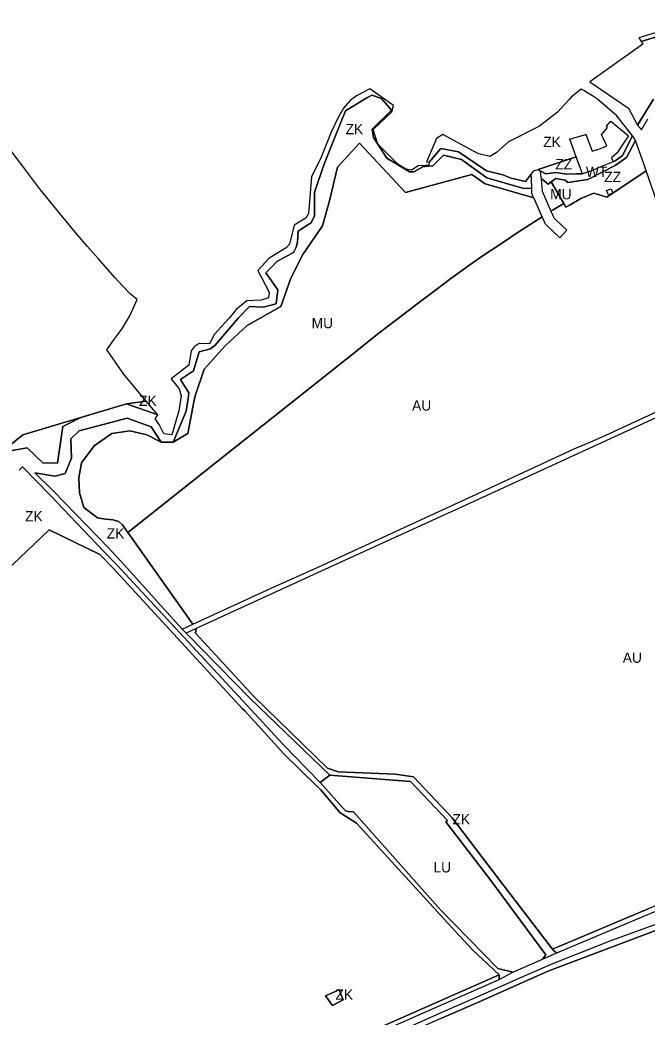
# Model space of a CAD drawing. Extents: x -522079 to -518833, y -1142398 to -1139961.
# Drawn here: x -521599 to -520990, y -1141061 to -1140093 of the extents above; entities that cross this region are included whole.
import ezdxf

# ---------------------------------------------------------------- set-up
doc = ezdxf.new("R2010")
doc.units = 0
for name, color, linetype in [('90640013', 7, 'Continuous'), ('90670013', 7, 'Continuous'), ('90710013', 7, 'Continuous'), ('90710023', 7, 'Continuous'), ('90750013', 7, 'Continuous'), ('90770013', 7, 'Continuous'), ('90830013', 7, 'Continuous')]:
    doc.layers.add(name, color=color, linetype=linetype)

msp = doc.modelspace()

# ---------------------------------------------------------------- linework, layer by layer
at = {"layer": '90640013'}
for points in [[(-520941.45, -1140093.01), (-520998.41, -1140110.24), (-520996.26, -1140113.95), (-520964.33, -1140104.24)], [(-521462.16, -1140502.96), (-521450.52, -1140503.04), (-521437.98, -1140472.83), (-521435.8, -1140458.35), (-521435.3, -1140455), (-521443.44, -1140442.21), (-521430.97, -1140433.67), (-521425.29, -1140415.18), (-521414.4, -1140412.25), (-521409.97, -1140408.74), (-521387.23, -1140382.25), (-521376.68, -1140371.11), (-521363.37, -1140371.78), (-521350.48, -1140368.68), (-521348.98, -1140355.15), (-521360.62, -1140338.49), (-521354.5, -1140332.33), (-521349.83, -1140327.64), (-521333.68, -1140318.76), (-521331.35, -1140313.68), (-521329.93, -1140308.65), (-521329.18, -1140298.1), (-521319.77, -1140291.98), (-521316.7, -1140289.98), (-521313.45, -1140283.14), (-521313.53, -1140260.28), (-521303.57, -1140232.09), (-521288.02, -1140193.37), (-521283.26, -1140181.41), (-521262.49, -1140168.67), (-521260.08, -1140167.19), (-521257.73, -1140166.05), (-521248.42, -1140169.45), (-521238.63, -1140180.63), (-521257.36, -1140198.93), (-521256.03, -1140207.29), (-521243.23, -1140227.2), (-521221.12, -1140240.34), (-521217.02, -1140240.66), (-521208.19, -1140235.66), (-521205.87, -1140235.43), (-521198.5, -1140234.71), (-521188.13, -1140224.34), (-521170.61, -1140228.65), (-521146.04, -1140246.18), (-521110.27, -1140256.62), (-521102.44, -1140256.49), (-521102.76, -1140247.73), (-521102.93, -1140242.86), (-521108.36, -1140249.87), (-521122.43, -1140246.78), (-521130.62, -1140243.41), (-521146.28, -1140239.39), (-521156.43, -1140232.87), (-521173.55, -1140221.12), (-521190.8, -1140217.9), (-521202.15, -1140231.14), (-521202.32, -1140233.95), (-521205.52, -1140234.19), (-521212.75, -1140234.73), (-521219.26, -1140238.96), (-521224.62, -1140237.78), (-521232.49, -1140232.94), (-521251.89, -1140213.49), (-521256.3, -1140199.5), (-521238.42, -1140182.36), (-521236.81, -1140176.19), (-521259.67, -1140159.99), (-521265.75, -1140163.05), (-521272.67, -1140166.78), (-521278.81, -1140171.17), (-521285.21, -1140178.6), (-521290.54, -1140187.61), (-521297.37, -1140201.85), (-521306.79, -1140226.13), (-521316.46, -1140245.31), (-521319.14, -1140281.01), (-521321.89, -1140285.5), (-521333.16, -1140292.26), (-521337.76, -1140310.68), (-521340.77, -1140314.23), (-521357.43, -1140324.38), (-521368.43, -1140336.25), (-521357.5, -1140357.21), (-521358.18, -1140362.8), (-521365.2, -1140365.12), (-521379.07, -1140365.7), (-521389.35, -1140374.32), (-521396.32, -1140382.62), (-521403.86, -1140390.75), (-521410.38, -1140398.05), (-521415.37, -1140407.41), (-521425.52, -1140407.15), (-521430.32, -1140410.33), (-521433.21, -1140414.4), (-521435.44, -1140428.3), (-521452.48, -1140441.66), (-521444.82, -1140451.17), (-521442.88, -1140458.09), (-521445.06, -1140472.47), (-521451.98, -1140495.75), (-521459.62, -1140494.93), (-521464.21, -1140485.93), (-521468.11, -1140480.32), (-521465.61, -1140476.61), (-521496.06, -1140465.78), (-521540.23, -1140479.04), (-521557.78, -1140487.71), (-521562.91, -1140523.45), (-521577.07, -1140523.11), (-521592.51, -1140508.64), (-521606.9, -1140511.13)], [(-520984.14, -1140169.84), (-520999.73, -1140195.29), (-520997.26, -1140198.03), (-520995.82, -1140199.62), (-520989.57, -1140189.1)], [(-521053.25, -1140242.58), (-521058.99, -1140242.45), (-521068.77, -1140242.91), (-521079.19, -1140241.03), (-521088.86, -1140242.57), (-521094.12, -1140239.48), (-521093.8, -1140243.17), (-521093.43, -1140247.58), (-521092.43, -1140247.55), (-521086.36, -1140252.38), (-521083.46, -1140250.25), (-521079.08, -1140247.03), (-521070.02, -1140248.6), (-521067.28, -1140250.75), (-521047.85, -1140248.01), (-521021.33, -1140234.46), (-521010.26, -1140226.65), (-521001.72, -1140210.08), (-521002.93, -1140207.73), (-521004.56, -1140205.45), (-521014.41, -1140224.73), (-521021.33, -1140229.82), (-521023.4, -1140230.68), (-521037.86, -1140236.76), (-521042.48, -1140238.76), (-521053.25, -1140242.58)], [(-521600.31, -1140530.11), (-521598.04, -1140528.01), (-521596.8, -1140526.87), (-521570.34, -1140553.98), (-521517.85, -1140609.14), (-521505.44, -1140622.18), (-521379.23, -1140758.51), (-521344.11, -1140796.22), (-521307.86, -1140833.61), (-521298.55, -1140826.47), (-521375.87, -1140751.79), (-521438.02, -1140688.47), (-521441.99, -1140684.63), (-521501.14, -1140618.78), (-521510.5, -1140608.85), (-521513.48, -1140605.69), (-521566.82, -1140550.59), (-521584.91, -1140532.83), (-521565.66, -1140535.94), (-521555.6, -1140533.49), (-521549.24, -1140518.67), (-521549.91, -1140499.85), (-521541.79, -1140492.15), (-521495.23, -1140479.84), (-521471.95, -1140488.22), (-521462.16, -1140502.96)]]:
    msp.add_lwpolyline(points, dxfattribs=at)
at = {"layer": '90670013'}
for points in [[(-521071.39, -1140271.24), (-521069.26, -1140274.95), (-521065.28, -1140272.43), (-521054.61, -1140266.48), (-521042, -1140261.25), (-521029.36, -1140265.01), (-520991.34, -1140239.5), (-520993.36, -1140233.77), (-521001.72, -1140210.08), (-521010.26, -1140226.65), (-521021.33, -1140234.46), (-521047.85, -1140248.01), (-521067.28, -1140250.75), (-521070.02, -1140248.6), (-521079.08, -1140247.03), (-521083.46, -1140250.25), (-521071.39, -1140271.24)], [(-521029.71, -1140258.76), (-521025.45, -1140257.06), (-521023.8, -1140261.15), (-521027.96, -1140262.97), (-521029.71, -1140258.76)]]:
    msp.add_lwpolyline(points, dxfattribs=at)
msp.add_lwpolyline([(-521053.25, -1140242.58), (-521059.29, -1140225.79), (-521096.26, -1140238.22), (-521094.12, -1140239.48), (-521088.86, -1140242.57), (-521079.19, -1140241.03), (-521068.77, -1140242.91), (-521058.99, -1140242.45)], close=True, dxfattribs=at)
at = {"layer": '90710013'}
for points in [[(-520964.33, -1140104.24), (-520996.26, -1140113.95), (-520994.7, -1140116.62), (-521045.99, -1140153.16), (-521008.55, -1140178.79), (-520999.73, -1140195.29), (-520984.14, -1140169.84)], [(-521450.52, -1140503.04), (-521436.3, -1140494.58), (-521430.55, -1140463.89), (-521429.44, -1140457.98), (-521420.52, -1140431.99), (-521399.96, -1140409.23), (-521378.73, -1140389.63), (-521346.04, -1140371.4), (-521336.24, -1140343.91), (-521324.74, -1140320.75), (-521305.66, -1140292.85), (-521298.91, -1140268.76), (-521291.01, -1140236.12), (-521269.84, -1140212.73), (-521224.97, -1140260.52), (-521160.59, -1140243.23), (-521147.75, -1140252.04), (-521100.5, -1140265.83), (-521102.24, -1140261.94), (-521102.44, -1140256.49), (-521110.27, -1140256.62), (-521146.04, -1140246.18), (-521170.61, -1140228.65), (-521188.13, -1140224.34), (-521198.5, -1140234.71), (-521205.87, -1140235.43), (-521208.19, -1140235.66), (-521217.02, -1140240.66), (-521221.12, -1140240.34), (-521243.23, -1140227.2), (-521256.03, -1140207.29), (-521257.36, -1140198.93), (-521238.63, -1140180.63), (-521248.42, -1140169.45), (-521257.73, -1140166.05), (-521260.08, -1140167.19), (-521262.49, -1140168.67), (-521283.26, -1140181.41), (-521288.02, -1140193.37), (-521303.57, -1140232.09), (-521313.53, -1140260.28), (-521313.45, -1140283.14), (-521316.7, -1140289.98), (-521319.77, -1140291.98), (-521329.18, -1140298.1), (-521329.93, -1140308.65), (-521331.35, -1140313.68), (-521333.68, -1140318.76), (-521349.83, -1140327.64), (-521354.5, -1140332.33), (-521360.62, -1140338.49), (-521348.98, -1140355.15), (-521350.48, -1140368.68), (-521363.37, -1140371.78), (-521376.68, -1140371.11), (-521387.23, -1140382.25), (-521409.97, -1140408.74), (-521414.4, -1140412.25), (-521425.29, -1140415.18), (-521430.97, -1140433.67), (-521443.44, -1140442.21), (-521435.3, -1140455), (-521435.8, -1140458.35), (-521437.98, -1140472.83), (-521450.52, -1140503.04)], [(-521102.93, -1140242.86), (-521100.42, -1140239.62), (-521096.26, -1140238.22), (-521059.29, -1140225.79), (-521065.43, -1140208.69), (-521060.17, -1140207.15), (-521052.23, -1140204.77), (-521050.38, -1140204.23), (-521049.86, -1140204.08), (-521044.31, -1140218.8), (-521043.73, -1140220.34), (-521039.84, -1140219.26), (-521038.87, -1140219.06), (-521029.59, -1140215.24), (-521032.9, -1140208.45), (-521034.61, -1140204.63), (-521028.73, -1140197.48), (-521029.89, -1140196.26), (-521025.79, -1140191.41), (-521008.43, -1140205.69), (-521011.89, -1140210.69), (-521019.95, -1140222.33), (-521024.94, -1140227.06), (-521023.4, -1140230.68), (-521021.33, -1140229.82), (-521014.41, -1140224.73), (-521004.56, -1140205.45), (-521019.82, -1140186.27), (-521038.45, -1140170.03), (-521042.52, -1140167.42), (-521047.19, -1140164.44), (-521051.86, -1140161.45), (-521054.36, -1140160.13), (-521063.7, -1140167.77), (-521066.01, -1140170.35), (-521077.51, -1140182.69), (-521094.81, -1140196.05), (-521124.89, -1140211.23), (-521136.78, -1140221.72), (-521142.98, -1140225.64), (-521153.92, -1140223.1), (-521159.02, -1140220.32), (-521188.9, -1140204.31), (-521194.92, -1140208.09), (-521204.62, -1140230.71), (-521202.15, -1140231.14), (-521190.8, -1140217.9), (-521173.55, -1140221.12), (-521156.43, -1140232.87), (-521146.28, -1140239.39), (-521130.62, -1140243.41), (-521122.43, -1140246.78), (-521108.36, -1140249.87), (-521102.93, -1140242.86)], [(-521465.61, -1140476.61), (-521476.87, -1140463.06), (-521496.06, -1140465.78), (-521465.61, -1140476.61)], [(-521606.9, -1140511.13), (-521592.51, -1140508.64), (-521577.07, -1140523.11), (-521562.91, -1140523.45), (-521557.78, -1140487.71), (-521540.23, -1140479.04), (-521596.59, -1140495.96), (-521619, -1140513.52)], [(-521462.16, -1140502.96), (-521471.95, -1140488.22), (-521495.23, -1140479.84), (-521541.79, -1140492.15), (-521549.91, -1140499.85), (-521549.24, -1140518.67), (-521555.6, -1140533.49), (-521565.66, -1140535.94), (-521584.91, -1140532.83), (-521566.82, -1140550.59), (-521513.48, -1140605.69), (-521510.5, -1140608.85), (-521501.14, -1140618.78), (-521441.99, -1140684.63), (-521431.42, -1140679.77), (-521484.19, -1140605.4), (-521492.01, -1140594.38), (-521494.62, -1140590.69), (-521496.32, -1140588.3), (-521499.98, -1140583.25), (-521503.43, -1140580.09), (-521509.23, -1140578.46), (-521516.38, -1140577.7), (-521524.24, -1140576.46), (-521537.25, -1140566.46), (-521541.63, -1140552.23), (-521542.41, -1140537.54), (-521539.58, -1140523.18), (-521527.29, -1140506.41), (-521510.34, -1140494.68), (-521492.65, -1140492.08), (-521476.06, -1140495.98), (-521462.16, -1140502.96)], [(-521120.79, -1141017.67), (-521135.25, -1141014.2), (-521191.17, -1140957.11), (-521275.9, -1140861.47), (-521279.53, -1140861.89), (-521283.37, -1140860.94), (-521307.86, -1140833.61), (-521344.11, -1140796.22), (-521379.23, -1140758.51), (-521505.44, -1140622.18), (-521517.85, -1140609.14), (-521570.34, -1140553.98), (-521596.8, -1140526.87), (-521598.04, -1140528.01), (-521600.31, -1140530.11)], [(-521620.49, -1140635.2), (-521571.05, -1140588.16), (-521521.75, -1140612.22), (-521509.24, -1140625.15), (-521424.45, -1140717.21), (-521383.31, -1140761.88), (-521381.12, -1140763.92), (-521343.03, -1140805.79), (-521311.05, -1140836.96), (-521307.59, -1140840.17), (-521288.46, -1140863.02), (-521283.24, -1140866.3), (-521272.67, -1140872.95), (-521180.73, -1140973.62), (-521160.03, -1140995.91), (-521134.23, -1141020.21), (-521134.18, -1141024.63), (-521120.79, -1141017.67)], [(-521082.3, -1140995.42), (-521133.42, -1140928.49), (-521179.82, -1140867.68), (-521217.11, -1140828.01), (-521234.98, -1140825.42), (-521290.3, -1140823.03), (-521300.72, -1140819.47), (-521372.2, -1140749.84), (-521386.59, -1140734.32), (-521428.9, -1140688.4), (-521428.47, -1140683.93), (-521438.02, -1140688.47), (-521375.87, -1140751.79), (-521298.55, -1140826.47), (-521220.23, -1140832.37), (-521184.18, -1140870.5), (-521185.72, -1140871.68), (-521143.12, -1140927.46), (-521088.9, -1141000.66), (-521091.97, -1141005.03), (-521077.97, -1140999.02), (-521081.12, -1140996.97), (-521082.3, -1140995.42)]]:
    msp.add_lwpolyline(points, dxfattribs=at)
msp.add_lwpolyline([(-521302.83, -1141040.76), (-521296.08, -1141050.04), (-521285.67, -1141044.64), (-521289.36, -1141034.73)], close=True, dxfattribs=at)
at = {"layer": '90710023'}
msp.add_lwpolyline([(-521082.3, -1140995.42), (-521081.12, -1140996.97), (-521077.97, -1140999.02), (-520987.34, -1140960.66), (-520896.33, -1140923.45), (-520882.47, -1140917.37), (-520890.08, -1140915.49), (-520894.6, -1140917.89), (-520989.26, -1140956.04)], close=True, dxfattribs=at)
for points in [[(-521190.59, -1141062.63), (-521154.28, -1141046.62), (-521111.47, -1141027.75), (-521085.77, -1141016.42), (-520964.29, -1140970.32), (-520959.78, -1140968.46), (-520892.3, -1140942.89), (-520893.74, -1140937.98), (-520956.56, -1140961.79), (-520970.5, -1140967.09), (-521026.59, -1140987.63), (-521082.18, -1141009.47), (-521112.83, -1141022.98), (-521155.63, -1141041.85), (-521191.96, -1141057.88), (-521222.3, -1141071.25)], [(-521134.23, -1141020.21), (-521271.3, -1141080.74), (-521274.53, -1141082.16), (-521472.07, -1141168.66), (-521476.67, -1141170.91), (-521705, -1141272.16), (-521696.71, -1141273.51), (-521531.28, -1141200.09), (-521478.81, -1141176.87), (-521464.85, -1141170.68), (-521354.37, -1141121.84), (-521271.86, -1141085.49), (-521262.72, -1141081.47), (-521223.67, -1141064.26), (-521134.18, -1141024.63), (-521134.23, -1141020.21)]]:
    msp.add_lwpolyline(points, dxfattribs=at)
at = {"layer": '90750013'}
for points in [[(-521619, -1140513.52), (-521596.59, -1140495.96), (-521540.23, -1140479.04), (-521496.06, -1140465.78), (-521476.87, -1140463.06), (-521498.88, -1140436.59), (-521509.46, -1140421.2), (-521515.07, -1140413.37), (-521508.32, -1140403.51), (-521500.52, -1140393.33), (-521492.65, -1140380.39), (-521485.71, -1140364.38), (-521487.26, -1140363.09), (-521492.09, -1140359.13), (-521499.72, -1140351.14), (-521507.29, -1140343.05), (-521523.43, -1140324.72), (-521534.06, -1140312.64), (-521541.69, -1140303.97), (-521544.01, -1140301.33), (-521560.73, -1140281.01), (-521579.62, -1140257.92), (-521596.95, -1140234.61), (-521608.33, -1140219.87)], [(-520978.89, -1140274.79), (-520991.34, -1140239.5), (-521029.36, -1140265.01), (-521042, -1140261.25), (-521054.61, -1140266.48), (-521065.28, -1140272.43), (-521069.26, -1140274.95), (-521071.39, -1140271.24), (-521081.77, -1140277.41), (-521083.79, -1140278.7), (-521081.89, -1140282.94), (-521081.11, -1140284.7), (-521080.73, -1140285.54), (-521072.76, -1140293.07), (-521068.35, -1140297.23), (-521075.22, -1140304.5), (-521081.54, -1140298.53), (-521089.05, -1140291.44), (-521089.34, -1140290.78), (-521090.43, -1140288.34), (-521092.32, -1140284.11)], [(-521092.32, -1140284.11), (-521115.76, -1140299), (-521130.86, -1140309.33), (-521148.51, -1140320.94), (-521160.13, -1140329.24), (-521181.05, -1140344.19), (-521190.73, -1140351.49), (-521212.85, -1140368.17), (-521233.39, -1140383.74), (-521245.45, -1140392.88), (-521252.22, -1140398.25), (-521274.04, -1140415.55), (-521389.53, -1140507.12), (-521494.62, -1140590.69), (-521492.01, -1140594.38), (-521484.19, -1140605.4), (-521431.42, -1140679.77), (-521355.48, -1140644.9), (-521309.07, -1140623.96), (-521152, -1140551.52), (-521060.49, -1140509.3), (-521045.09, -1140502.65), (-521031.07, -1140496.4), (-520911.89, -1140441.66)], [(-520909.31, -1140446.06), (-521038.29, -1140505.39), (-521174.07, -1140567.72), (-521187.8, -1140573.75), (-521306.81, -1140628.37), (-521428.47, -1140683.93), (-521428.9, -1140688.4), (-521386.59, -1140734.32), (-521372.2, -1140749.84), (-521300.72, -1140819.47), (-521290.3, -1140823.03), (-521234.98, -1140825.42), (-521217.11, -1140828.01), (-521179.82, -1140867.68), (-521133.42, -1140928.49), (-521082.3, -1140995.42), (-520989.26, -1140956.04)], [(-521134.23, -1141020.21), (-521160.03, -1140995.91), (-521180.73, -1140973.62), (-521272.67, -1140872.95), (-521283.24, -1140866.3), (-521288.46, -1140863.02), (-521307.59, -1140840.17), (-521311.05, -1140836.96), (-521343.03, -1140805.79), (-521381.12, -1140763.92), (-521383.31, -1140761.88), (-521424.45, -1140717.21), (-521509.24, -1140625.15), (-521521.75, -1140612.22), (-521571.05, -1140588.16), (-521620.49, -1140635.2)], [(-521271.3, -1141080.74), (-521134.23, -1141020.21)]]:
    msp.add_lwpolyline(points, dxfattribs=at)
for points in [[(-520727.16, -1141148.38), (-520733.88, -1141082.24), (-520846.14, -1141104.23), (-520847.24, -1141100.33), (-520861.45, -1141049.84), (-520872.93, -1141009.05), (-520881.52, -1140979.72), (-520885.58, -1140965.84), (-520888.93, -1140954.41), (-520892.3, -1140942.89), (-520959.78, -1140968.46), (-520964.29, -1140970.32), (-521085.77, -1141016.42), (-521111.47, -1141027.75), (-521154.28, -1141046.62), (-521190.59, -1141062.63), (-521216.29, -1141073.97), (-521143.42, -1141331.19), (-521117.38, -1141319.6), (-521081.35, -1141303.56), (-521038.45, -1141284.46), (-520895.96, -1141221.04), (-520890.16, -1141218.54)], [(-521302.83, -1141040.76), (-521289.36, -1141034.73), (-521285.67, -1141044.64), (-521296.08, -1141050.04)]]:
    msp.add_lwpolyline(points, close=True, dxfattribs=at)
at = {"layer": '90770013'}
msp.add_lwpolyline([(-521120.79, -1141017.67), (-521091.97, -1141005.03), (-521088.9, -1141000.66), (-521143.12, -1140927.46), (-521185.72, -1140871.68), (-521184.18, -1140870.5), (-521220.23, -1140832.37), (-521298.55, -1140826.47), (-521307.86, -1140833.61), (-521283.37, -1140860.94), (-521279.53, -1140861.89), (-521275.9, -1140861.47), (-521191.17, -1140957.11), (-521135.25, -1141014.2), (-521120.79, -1141017.67)], dxfattribs=at)
at = {"layer": '90830013'}
for points in [[(-521450.52, -1140503.04), (-521462.16, -1140502.96), (-521476.06, -1140495.98), (-521492.65, -1140492.08), (-521510.34, -1140494.68), (-521527.29, -1140506.41), (-521539.58, -1140523.18), (-521542.41, -1140537.54), (-521541.63, -1140552.23), (-521537.25, -1140566.46), (-521524.24, -1140576.46), (-521516.38, -1140577.7), (-521509.23, -1140578.46), (-521503.43, -1140580.09), (-521499.98, -1140583.25), (-521496.32, -1140588.3), (-521494.62, -1140590.69), (-521389.53, -1140507.12), (-521274.04, -1140415.55), (-521252.22, -1140398.25), (-521245.45, -1140392.88), (-521233.39, -1140383.74), (-521212.85, -1140368.17), (-521190.73, -1140351.49), (-521181.05, -1140344.19), (-521160.13, -1140329.24), (-521148.51, -1140320.94), (-521130.86, -1140309.33), (-521115.76, -1140299), (-521092.32, -1140284.11), (-521100.5, -1140265.83), (-521147.75, -1140252.04), (-521160.59, -1140243.23), (-521224.97, -1140260.52), (-521269.84, -1140212.73), (-521291.01, -1140236.12), (-521298.91, -1140268.76), (-521305.66, -1140292.85), (-521324.74, -1140320.75), (-521336.24, -1140343.91), (-521346.04, -1140371.4), (-521378.73, -1140389.63), (-521399.96, -1140409.23), (-521420.52, -1140431.99), (-521429.44, -1140457.98), (-521430.55, -1140463.89), (-521436.3, -1140494.58), (-521450.52, -1140503.04)], [(-521071.39, -1140271.24), (-521083.46, -1140250.25), (-521086.36, -1140252.38), (-521092.43, -1140247.55), (-521093.43, -1140247.58), (-521092.42, -1140259.41), (-521083.79, -1140278.7), (-521081.77, -1140277.41), (-521071.39, -1140271.24)]]:
    msp.add_lwpolyline(points, dxfattribs=at)

# ---------------------------------------------------------------- texts
at = {"layer": '90640013'}
msp.add_text('WT', height=10, rotation=360, dxfattribs=at).set_placement((-521049.82, -1140245.5))
at = {"layer": '90670013'}
for rotation, p in [(360, (-521079.58, -1140238.06)), (0, (-521032.05, -1140250.46))]:
    msp.add_text('ZZ', height=10, rotation=rotation, dxfattribs=at).set_placement(p)
at = {"layer": '90710013'}
for rotation, p in [(0, (-521283.25, -1140204.03)), (0, (-521091.27, -1140216.45)), (0, (-521483.78, -1140467.85)), (0, (-521594.46, -1140579.91)), (0, (-521515.14, -1140596.61)), (360, (-521179.41, -1140874.13)), (0, (-521293.05, -1141044.41))]:
    msp.add_text('ZK', height=10, rotation=rotation, dxfattribs=at).set_placement(p)
at = {"layer": '90750013'}
for p in [(-521218.63, -1140472.35), (-521014.03, -1140717.24)]:
    msp.add_text('AU', height=10, rotation=360, dxfattribs=at).set_placement(p)
at = {"layer": '90770013'}
msp.add_text('LU', height=10, rotation=0, dxfattribs=at).set_placement((-521197.88, -1140920.78))
at = {"layer": '90830013'}
for p in [(-521084.51, -1140267.23), (-521316.17, -1140392.33)]:
    msp.add_text('MU', height=10, rotation=0, dxfattribs=at).set_placement(p)

doc.saveas('drawing.dxf')
